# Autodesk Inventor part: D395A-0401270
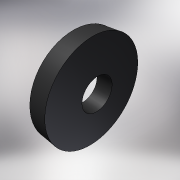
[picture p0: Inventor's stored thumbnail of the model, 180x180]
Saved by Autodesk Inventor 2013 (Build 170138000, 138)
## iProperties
Shininess: 69.0
Length Units: 11269
Angle Units: 11279
Time Units: 11290
Mass Units: 11283
Length Display Precision: 3
Angle Display Precision: 2
Created: 2002-06
Part Number: D395A-0401270
Material: Rubber
Document SubType Name: Modeling
Designer: LAlexey
Density: 0.93 g/cm^3
Mass: 2.92168 g
Surface Area: 18.8496 cm^2
Volume: 3.14159 cm^3
Density: 1.06
Volumn: 3.8900771033075623
Area: 34.55751918948772
PropertySet Name: Model Information
Control State: 0
Master: False
Checked Out: True
Author: LAlexey
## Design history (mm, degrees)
body "Solid1"
revolve "Revolution1" stored, may be unused: angle "d6" = 90 deg
sketch "Sketch1"
  geometry: L1 (0.27, 31.748)-(0.27, 41.748); L2 (0.27, 41.748)-(5.27, 41.748); L3 (5.27, 41.748)-(5.27, 31.748); L4 (5.27, 31.748)-(0.27, 31.748); L5 (6.357, 26.748)-(8.857, 26.748)
  constraints: 10 end point, 2 parallel, 1 vertical
  dimensions: "d1" = 5 distance between parallel lines of L5 L4; "d4" = 5 distance between parallel lines of L3 L1; "d5" = 15 distance between parallel lines of L5 L2
